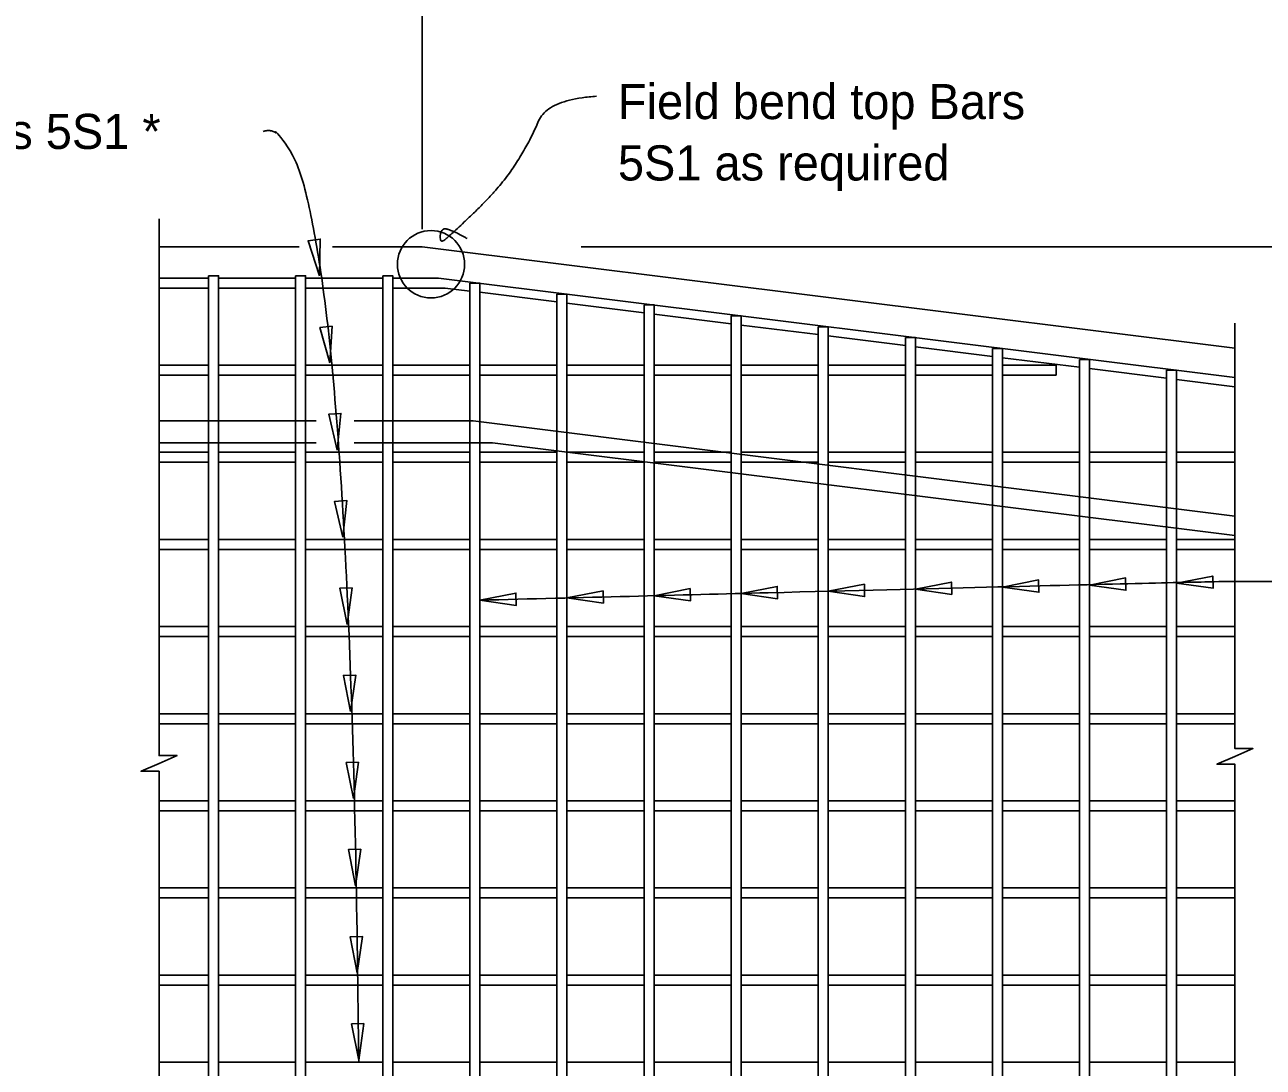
# Model space of a CAD drawing. Extents: x 120587.5 to 120659.6, y 120683.4 to 120715.5.
# Drawn here: x 120608.18 to 120615.29, y 120699.71 to 120705.69 of the extents above; entities that cross this region are included whole.
import ezdxf

# ---------------------------------------------------------------- set-up
doc = ezdxf.new("R2010")
doc.units = 0
for name, color, linetype in [('AdhocPoint_dp', 7, 'Continuous'), ('Border', 7, 'Continuous'), ('PlotBorder_dp', 7, 'Continuous'), ('TextMisc', 7, 'Continuous')]:
    doc.layers.add(name, color=color, linetype=linetype)

msp = doc.modelspace()

# ---------------------------------------------------------------- linework, layer by layer
at = {"layer": 'AdhocPoint_dp'}
for p, q in [((120610.4626, 120704.5212), (120610.4626, 120706.077)), ((120611.3758, 120704.4204), (120627.6224, 120704.4204))]:
    msp.add_line(p, q, dxfattribs=at)
for points in [[(120608.952, 120699.087), (120608.952, 120701.4106), (120608.8486, 120701.4106), (120608.952, 120701.4556), (120609.0553, 120701.5006), (120608.952, 120701.5006), (120608.952, 120704.5808)], [(120615.1274, 120701.1963), (120615.1274, 120701.4501), (120615.0241, 120701.4501), (120615.1274, 120701.4951), (120615.2308, 120701.5401), (120615.1274, 120701.5401), (120615.1274, 120703.9817)], [(120615.1275, 120697.6639), (120615.1275, 120698.7724), (120615.0241, 120698.7724), (120615.1275, 120698.8174), (120615.2308, 120698.8624), (120615.1275, 120698.8624), (120615.1275, 120701.1964)]]:
    msp.add_lwpolyline(points, dxfattribs=at)
for points in [[(120609.873, 120704.2532), (120609.8776, 120704.4644), (120609.8078, 120704.4541)], [(120609.932, 120703.7532), (120609.9456, 120703.964), (120609.8754, 120703.9567)], [(120609.9742, 120703.2532), (120609.9963, 120703.4633), (120609.9259, 120703.4588)], [(120610.0063, 120702.7532), (120610.03, 120702.9631), (120609.9596, 120702.9592)], [(120613.7933, 120702.4673), (120614.0024, 120702.4374), (120614.0006, 120702.5079)], [(120614.2933, 120702.479), (120614.5024, 120702.4491), (120614.5006, 120702.5196)], [(120614.7933, 120702.4899), (120615.0024, 120702.46), (120615.0006, 120702.5306)], [(120610.0315, 120702.2532), (120610.0598, 120702.4625), (120609.9892, 120702.4602)], [(120611.2933, 120702.4048), (120611.5024, 120702.3749), (120611.5006, 120702.4454)], [(120611.7933, 120702.4175), (120612.0024, 120702.3876), (120612.0006, 120702.4582)], [(120612.2933, 120702.4302), (120612.5024, 120702.4003), (120612.5006, 120702.4708)], [(120612.7933, 120702.4428), (120613.0024, 120702.4129), (120613.0006, 120702.4834)], [(120613.2933, 120702.4551), (120613.5024, 120702.4253), (120613.5006, 120702.4958)], [(120610.7933, 120702.3919), (120611.0024, 120702.362), (120611.0006, 120702.4326)], [(120610.0515, 120701.7532), (120610.0809, 120701.9624), (120610.0104, 120701.9604)], [(120610.0674, 120701.2532), (120610.0968, 120701.4624), (120610.0263, 120701.4604)], [(120610.0801, 120700.7532), (120610.1095, 120700.9624), (120610.039, 120700.9604)], [(120610.0901, 120700.2532), (120610.1195, 120700.4624), (120610.049, 120700.4604)], [(120610.0978, 120699.7532), (120610.1272, 120699.9624), (120610.0567, 120699.9604)]]:
    msp.add_lwpolyline(points, close=True, dxfattribs=at)
msp.add_circle((120610.513, 120704.3194), 0.1931, dxfattribs=at)
for points in [[(120611.4622, 120705.2833), (120611.1816, 120705.2655), (120611.0751, 120705.0092), (120610.9028, 120704.7512), (120610.6053, 120704.4678), (120610.566, 120704.4427), (120610.566, 120704.5107), (120610.6053, 120704.5321), (120610.7197, 120704.4678)], [(120610.0983, 120699.7406), (120610.0465, 120705.2434), (120609.5504, 120705.0822)], [(120615.4491, 120702.4991), (120615.217, 120702.4991), (120614.9491, 120702.4991), (120610.7933, 120702.3919)]]:
    msp.add_open_spline(points, degree=2, dxfattribs=at)
at = {"layer": 'Border'}
for p, q in [((120609.236, 120704.2406), (120608.952, 120704.2406)), ((120609.736, 120704.2406), (120609.2933, 120704.2406)), ((120610.236, 120704.2406), (120609.7933, 120704.2406)), ((120610.5565, 120704.2406), (120610.2933, 120704.2406)), ((120610.5565, 120704.2406), (120615.1275, 120703.6693)), ((120609.236, 120704.1833), (120608.952, 120704.1833)), ((120609.736, 120704.1833), (120609.2933, 120704.1833)), ((120610.236, 120704.1833), (120609.7933, 120704.1833)), ((120610.5949, 120704.1833), (120610.2933, 120704.1833)), ((120610.5949, 120704.1833), (120610.736, 120704.1657)), ((120610.7933, 120704.1585), (120611.236, 120704.1032)), ((120611.2933, 120704.096), (120611.736, 120704.0407)), ((120611.7933, 120704.0335), (120612.236, 120703.9782)), ((120612.2933, 120703.971), (120612.736, 120703.9157)), ((120612.7933, 120703.9085), (120613.236, 120703.8532)), ((120613.2933, 120703.846), (120613.736, 120703.7907)), ((120609.236, 120703.7406), (120608.952, 120703.7406)), ((120609.736, 120703.7406), (120609.2933, 120703.7406)), ((120610.236, 120703.7406), (120609.7933, 120703.7406)), ((120610.736, 120703.7406), (120610.2933, 120703.7406)), ((120611.236, 120703.7406), (120610.7933, 120703.7406)), ((120611.736, 120703.7406), (120611.2933, 120703.7406)), ((120612.236, 120703.7406), (120611.7933, 120703.7406)), ((120612.736, 120703.7406), (120612.2933, 120703.7406)), ((120613.236, 120703.7406), (120612.7933, 120703.7406)), ((120613.736, 120703.7406), (120613.2933, 120703.7406)), ((120613.7933, 120703.7835), (120614.236, 120703.7282)), ((120614.1021, 120703.7406), (120613.7933, 120703.7406)), ((120614.1021, 120703.7406), (120614.1021, 120703.6833)), ((120614.2933, 120703.721), (120614.736, 120703.6657)), ((120609.236, 120703.6833), (120608.952, 120703.6833)), ((120609.736, 120703.6833), (120609.2933, 120703.6833)), ((120610.236, 120703.6833), (120609.7933, 120703.6833)), ((120610.736, 120703.6833), (120610.2933, 120703.6833)), ((120611.236, 120703.6833), (120610.7933, 120703.6833)), ((120611.736, 120703.6833), (120611.2933, 120703.6833)), ((120612.236, 120703.6833), (120611.7933, 120703.6833)), ((120612.736, 120703.6833), (120612.2933, 120703.6833)), ((120613.236, 120703.6833), (120612.7933, 120703.6833)), ((120613.736, 120703.6833), (120613.2933, 120703.6833)), ((120614.1021, 120703.6833), (120613.7933, 120703.6833)), ((120614.7933, 120703.6585), (120615.1275, 120703.6168)), ((120609.236, 120703.2406), (120608.952, 120703.2406)), ((120609.736, 120703.2406), (120609.2933, 120703.2406)), ((120610.236, 120703.2406), (120609.7933, 120703.2406)), ((120610.736, 120703.2406), (120610.2933, 120703.2406)), ((120611.236, 120703.2406), (120610.7933, 120703.2406)), ((120611.736, 120703.2406), (120611.2933, 120703.2406)), ((120612.236, 120703.2406), (120611.7933, 120703.2406)), ((120612.736, 120703.2406), (120612.2933, 120703.2406)), ((120613.236, 120703.2406), (120612.7933, 120703.2406)), ((120613.736, 120703.2406), (120613.2933, 120703.2406)), ((120614.236, 120703.2406), (120613.7933, 120703.2406)), ((120614.736, 120703.2406), (120614.2933, 120703.2406)), ((120615.1275, 120703.2406), (120614.7933, 120703.2406)), ((120609.236, 120703.1833), (120608.952, 120703.1833)), ((120609.736, 120703.1833), (120609.2933, 120703.1833)), ((120610.236, 120703.1833), (120609.7933, 120703.1833)), ((120610.736, 120703.1833), (120610.2933, 120703.1833)), ((120611.236, 120703.1833), (120610.7933, 120703.1833)), ((120611.736, 120703.1833), (120611.2933, 120703.1833)), ((120612.236, 120703.1833), (120611.7933, 120703.1833)), ((120612.736, 120703.1833), (120612.2933, 120703.1833)), ((120613.236, 120703.1833), (120612.7933, 120703.1833)), ((120613.736, 120703.1833), (120613.2933, 120703.1833)), ((120614.236, 120703.1833), (120613.7933, 120703.1833)), ((120614.736, 120703.1833), (120614.2933, 120703.1833)), ((120615.1275, 120703.1833), (120614.7933, 120703.1833)), ((120609.236, 120702.7406), (120608.952, 120702.7406)), ((120609.736, 120702.7406), (120609.2933, 120702.7406)), ((120610.236, 120702.7406), (120609.7933, 120702.7406)), ((120610.736, 120702.7406), (120610.2933, 120702.7406)), ((120611.236, 120702.7406), (120610.7933, 120702.7406)), ((120611.736, 120702.7406), (120611.2933, 120702.7406)), ((120612.236, 120702.7406), (120611.7933, 120702.7406)), ((120612.736, 120702.7406), (120612.2933, 120702.7406)), ((120613.236, 120702.7406), (120612.7933, 120702.7406)), ((120613.736, 120702.7406), (120613.2933, 120702.7406)), ((120614.236, 120702.7406), (120613.7933, 120702.7406)), ((120614.736, 120702.7406), (120614.2933, 120702.7406)), ((120615.1275, 120702.7406), (120614.7933, 120702.7406)), ((120609.236, 120702.6833), (120608.952, 120702.6833)), ((120609.736, 120702.6833), (120609.2933, 120702.6833)), ((120610.236, 120702.6833), (120609.7933, 120702.6833)), ((120610.736, 120702.6833), (120610.2933, 120702.6833)), ((120611.236, 120702.6833), (120610.7933, 120702.6833)), ((120611.736, 120702.6833), (120611.2933, 120702.6833)), ((120612.236, 120702.6833), (120611.7933, 120702.6833)), ((120612.736, 120702.6833), (120612.2933, 120702.6833)), ((120613.236, 120702.6833), (120612.7933, 120702.6833)), ((120613.736, 120702.6833), (120613.2933, 120702.6833)), ((120614.236, 120702.6833), (120613.7933, 120702.6833)), ((120614.736, 120702.6833), (120614.2933, 120702.6833)), ((120615.1275, 120702.6833), (120614.7933, 120702.6833)), ((120609.236, 120702.2406), (120608.952, 120702.2406)), ((120609.736, 120702.2406), (120609.2933, 120702.2406)), ((120610.236, 120702.2406), (120609.7933, 120702.2406)), ((120610.736, 120702.2406), (120610.2933, 120702.2406)), ((120611.236, 120702.2406), (120610.7933, 120702.2406)), ((120611.736, 120702.2406), (120611.2933, 120702.2406)), ((120612.236, 120702.2406), (120611.7933, 120702.2406)), ((120612.736, 120702.2406), (120612.2933, 120702.2406)), ((120613.236, 120702.2406), (120612.7933, 120702.2406)), ((120613.736, 120702.2406), (120613.2933, 120702.2406)), ((120614.236, 120702.2406), (120613.7933, 120702.2406)), ((120614.736, 120702.2406), (120614.2933, 120702.2406)), ((120615.1275, 120702.2406), (120614.7933, 120702.2406)), ((120609.236, 120702.1833), (120608.952, 120702.1833)), ((120609.736, 120702.1833), (120609.2933, 120702.1833)), ((120610.236, 120702.1833), (120609.7933, 120702.1833)), ((120610.736, 120702.1833), (120610.2933, 120702.1833)), ((120611.236, 120702.1833), (120610.7933, 120702.1833)), ((120611.736, 120702.1833), (120611.2933, 120702.1833)), ((120612.236, 120702.1833), (120611.7933, 120702.1833)), ((120612.736, 120702.1833), (120612.2933, 120702.1833)), ((120613.236, 120702.1833), (120612.7933, 120702.1833)), ((120613.736, 120702.1833), (120613.2933, 120702.1833)), ((120614.236, 120702.1833), (120613.7933, 120702.1833)), ((120614.736, 120702.1833), (120614.2933, 120702.1833)), ((120615.1275, 120702.1833), (120614.7933, 120702.1833)), ((120609.236, 120701.7406), (120608.952, 120701.7406)), ((120609.736, 120701.7406), (120609.2933, 120701.7406)), ((120610.236, 120701.7406), (120609.7933, 120701.7406)), ((120610.736, 120701.7406), (120610.2933, 120701.7406)), ((120611.236, 120701.7406), (120610.7933, 120701.7406)), ((120611.736, 120701.7406), (120611.2933, 120701.7406)), ((120612.236, 120701.7406), (120611.7933, 120701.7406)), ((120612.736, 120701.7406), (120612.2933, 120701.7406)), ((120613.236, 120701.7406), (120612.7933, 120701.7406)), ((120613.736, 120701.7406), (120613.2933, 120701.7406)), ((120614.236, 120701.7406), (120613.7933, 120701.7406)), ((120614.736, 120701.7406), (120614.2933, 120701.7406)), ((120615.1275, 120701.7406), (120614.7933, 120701.7406)), ((120609.236, 120701.6833), (120608.952, 120701.6833)), ((120609.736, 120701.6833), (120609.2933, 120701.6833)), ((120610.236, 120701.6833), (120609.7933, 120701.6833)), ((120610.736, 120701.6833), (120610.2933, 120701.6833)), ((120611.236, 120701.6833), (120610.7933, 120701.6833)), ((120611.736, 120701.6833), (120611.2933, 120701.6833)), ((120612.236, 120701.6833), (120611.7933, 120701.6833)), ((120612.736, 120701.6833), (120612.2933, 120701.6833)), ((120613.236, 120701.6833), (120612.7933, 120701.6833)), ((120613.736, 120701.6833), (120613.2933, 120701.6833)), ((120614.236, 120701.6833), (120613.7933, 120701.6833)), ((120614.736, 120701.6833), (120614.2933, 120701.6833)), ((120615.1275, 120701.6833), (120614.7933, 120701.6833)), ((120609.236, 120701.2406), (120608.952, 120701.2406)), ((120609.736, 120701.2406), (120609.2933, 120701.2406)), ((120610.236, 120701.2406), (120609.7933, 120701.2406)), ((120610.736, 120701.2406), (120610.2933, 120701.2406)), ((120611.236, 120701.2406), (120610.7933, 120701.2406)), ((120611.736, 120701.2406), (120611.2933, 120701.2406)), ((120612.236, 120701.2406), (120611.7933, 120701.2406)), ((120612.736, 120701.2406), (120612.2933, 120701.2406)), ((120613.236, 120701.2406), (120612.7933, 120701.2406)), ((120613.736, 120701.2406), (120613.2933, 120701.2406)), ((120614.236, 120701.2406), (120613.7933, 120701.2406)), ((120614.736, 120701.2406), (120614.2933, 120701.2406)), ((120615.1275, 120701.2406), (120614.7933, 120701.2406)), ((120609.236, 120701.1833), (120608.952, 120701.1833)), ((120609.736, 120701.1833), (120609.2933, 120701.1833)), ((120610.236, 120701.1833), (120609.7933, 120701.1833)), ((120610.736, 120701.1833), (120610.2933, 120701.1833)), ((120611.236, 120701.1833), (120610.7933, 120701.1833)), ((120611.736, 120701.1833), (120611.2933, 120701.1833)), ((120612.236, 120701.1833), (120611.7933, 120701.1833)), ((120612.736, 120701.1833), (120612.2933, 120701.1833)), ((120613.236, 120701.1833), (120612.7933, 120701.1833)), ((120613.736, 120701.1833), (120613.2933, 120701.1833)), ((120614.236, 120701.1833), (120613.7933, 120701.1833)), ((120614.736, 120701.1833), (120614.2933, 120701.1833)), ((120615.1275, 120701.1833), (120614.7933, 120701.1833)), ((120609.236, 120700.7406), (120608.952, 120700.7406)), ((120609.736, 120700.7406), (120609.2933, 120700.7406)), ((120610.236, 120700.7406), (120609.7933, 120700.7406)), ((120610.736, 120700.7406), (120610.2933, 120700.7406)), ((120611.236, 120700.7406), (120610.7933, 120700.7406)), ((120611.736, 120700.7406), (120611.2933, 120700.7406)), ((120612.236, 120700.7406), (120611.7933, 120700.7406)), ((120612.736, 120700.7406), (120612.2933, 120700.7406)), ((120613.236, 120700.7406), (120612.7933, 120700.7406)), ((120613.736, 120700.7406), (120613.2933, 120700.7406)), ((120614.236, 120700.7406), (120613.7933, 120700.7406)), ((120614.736, 120700.7406), (120614.2933, 120700.7406)), ((120615.1275, 120700.7406), (120614.7933, 120700.7406)), ((120609.236, 120700.6833), (120608.952, 120700.6833)), ((120609.736, 120700.6833), (120609.2933, 120700.6833)), ((120610.236, 120700.6833), (120609.7933, 120700.6833)), ((120610.736, 120700.6833), (120610.2933, 120700.6833)), ((120611.236, 120700.6833), (120610.7933, 120700.6833)), ((120611.736, 120700.6833), (120611.2933, 120700.6833)), ((120612.236, 120700.6833), (120611.7933, 120700.6833)), ((120612.736, 120700.6833), (120612.2933, 120700.6833)), ((120613.236, 120700.6833), (120612.7933, 120700.6833)), ((120613.736, 120700.6833), (120613.2933, 120700.6833)), ((120614.236, 120700.6833), (120613.7933, 120700.6833)), ((120614.736, 120700.6833), (120614.2933, 120700.6833)), ((120615.1275, 120700.6833), (120614.7933, 120700.6833)), ((120609.236, 120700.2406), (120608.952, 120700.2406)), ((120609.736, 120700.2406), (120609.2933, 120700.2406)), ((120610.236, 120700.2406), (120609.7933, 120700.2406)), ((120610.736, 120700.2406), (120610.2933, 120700.2406)), ((120611.236, 120700.2406), (120610.7933, 120700.2406)), ((120611.736, 120700.2406), (120611.2933, 120700.2406)), ((120612.236, 120700.2406), (120611.7933, 120700.2406)), ((120612.736, 120700.2406), (120612.2933, 120700.2406)), ((120613.236, 120700.2406), (120612.7933, 120700.2406)), ((120613.736, 120700.2406), (120613.2933, 120700.2406)), ((120614.236, 120700.2406), (120613.7933, 120700.2406)), ((120614.736, 120700.2406), (120614.2933, 120700.2406)), ((120615.1275, 120700.2406), (120614.7933, 120700.2406)), ((120609.236, 120700.1833), (120608.952, 120700.1833)), ((120609.736, 120700.1833), (120609.2933, 120700.1833)), ((120610.236, 120700.1833), (120609.7933, 120700.1833)), ((120610.736, 120700.1833), (120610.2933, 120700.1833)), ((120611.236, 120700.1833), (120610.7933, 120700.1833)), ((120611.736, 120700.1833), (120611.2933, 120700.1833)), ((120612.236, 120700.1833), (120611.7933, 120700.1833)), ((120612.736, 120700.1833), (120612.2933, 120700.1833)), ((120613.236, 120700.1833), (120612.7933, 120700.1833)), ((120613.736, 120700.1833), (120613.2933, 120700.1833)), ((120614.236, 120700.1833), (120613.7933, 120700.1833)), ((120614.736, 120700.1833), (120614.2933, 120700.1833)), ((120615.1275, 120700.1833), (120614.7933, 120700.1833)), ((120609.236, 120699.7406), (120608.952, 120699.7406)), ((120609.736, 120699.7406), (120609.2933, 120699.7406)), ((120610.236, 120699.7406), (120609.7933, 120699.7406)), ((120610.736, 120699.7406), (120610.2933, 120699.7406)), ((120611.236, 120699.7406), (120610.7933, 120699.7406)), ((120611.736, 120699.7406), (120611.2933, 120699.7406)), ((120612.236, 120699.7406), (120611.7933, 120699.7406)), ((120612.736, 120699.7406), (120612.2933, 120699.7406)), ((120613.236, 120699.7406), (120612.7933, 120699.7406)), ((120613.736, 120699.7406), (120613.2933, 120699.7406)), ((120614.236, 120699.7406), (120613.7933, 120699.7406)), ((120614.236, 120699.7406), (120614.1385, 120699.7406)), ((120614.736, 120699.7406), (120614.2933, 120699.7406)), ((120615.1275, 120699.7406), (120614.7933, 120699.7406)), ((120615.1275, 120699.7406), (120614.8382, 120699.7406))]:
    msp.add_line(p, q, dxfattribs=at)
for points in [[(120609.236, 120704.2537), (120609.2933, 120704.2537), (120609.2933, 120696.4203), (120609.236, 120696.4203)], [(120609.736, 120704.2537), (120609.7933, 120704.2537), (120609.7933, 120696.4203), (120609.736, 120696.4203)], [(120610.236, 120704.2537), (120610.2933, 120704.2537), (120610.2933, 120696.4203), (120610.236, 120696.4203)], [(120610.736, 120704.211), (120610.7933, 120704.211), (120610.7933, 120696.4203), (120610.736, 120696.4203)], [(120611.236, 120704.1485), (120611.2933, 120704.1485), (120611.2933, 120696.4203), (120611.236, 120696.4203)], [(120611.736, 120704.086), (120611.7933, 120704.086), (120611.7933, 120696.4203), (120611.736, 120696.4203)], [(120612.236, 120704.0235), (120612.2933, 120704.0235), (120612.2933, 120696.4203), (120612.236, 120696.4203)], [(120612.736, 120703.961), (120612.7933, 120703.961), (120612.7933, 120696.4203), (120612.736, 120696.4203)], [(120613.236, 120703.8985), (120613.2933, 120703.8985), (120613.2933, 120696.4203), (120613.236, 120696.4203)], [(120613.736, 120703.836), (120613.7933, 120703.836), (120613.7933, 120696.4203), (120613.736, 120696.4203)], [(120614.236, 120703.7735), (120614.2933, 120703.7735), (120614.2933, 120696.4203), (120614.236, 120696.4203)], [(120614.736, 120703.711), (120614.7933, 120703.711), (120614.7933, 120696.4203), (120614.736, 120696.4203)]]:
    msp.add_lwpolyline(points, close=True, dxfattribs=at)
at = {"layer": 'PlotBorder_dp'}
for p, q in [((120609.7562, 120704.4204), (120608.952, 120704.4204)), ((120610.4626, 120704.4204), (120609.9485, 120704.4204)), ((120610.4626, 120704.4204), (120615.1275, 120703.8373)), ((120608.952, 120703.4204), (120609.8533, 120703.4204)), ((120610.0721, 120703.4204), (120610.7547, 120703.4204)), ((120610.7547, 120703.4204), (120615.1275, 120702.8738)), ((120608.952, 120703.2954), (120609.8533, 120703.2954)), ((120610.0721, 120703.2954), (120610.8658, 120703.2954)), ((120610.8658, 120703.2954), (120615.1275, 120702.7627))]:
    msp.add_line(p, q, dxfattribs=at)

# ---------------------------------------------------------------- texts
at = {"layer": 'AdhocPoint_dp'}
for s, p in [('Field bend top Bars ', (120611.5859, 120705.1524)), ('5S1 as required', (120611.5859, 120704.8004))]:
    msp.add_text(s, height=0.2016, dxfattribs=at).set_placement(p)
at = {"layer": 'TextMisc'}
msp.add_text('Bars 5S1 *', height=0.2016, dxfattribs=at).set_placement((120607.6725, 120704.9811))

doc.saveas('drawing.dxf')
